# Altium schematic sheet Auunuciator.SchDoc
size A4
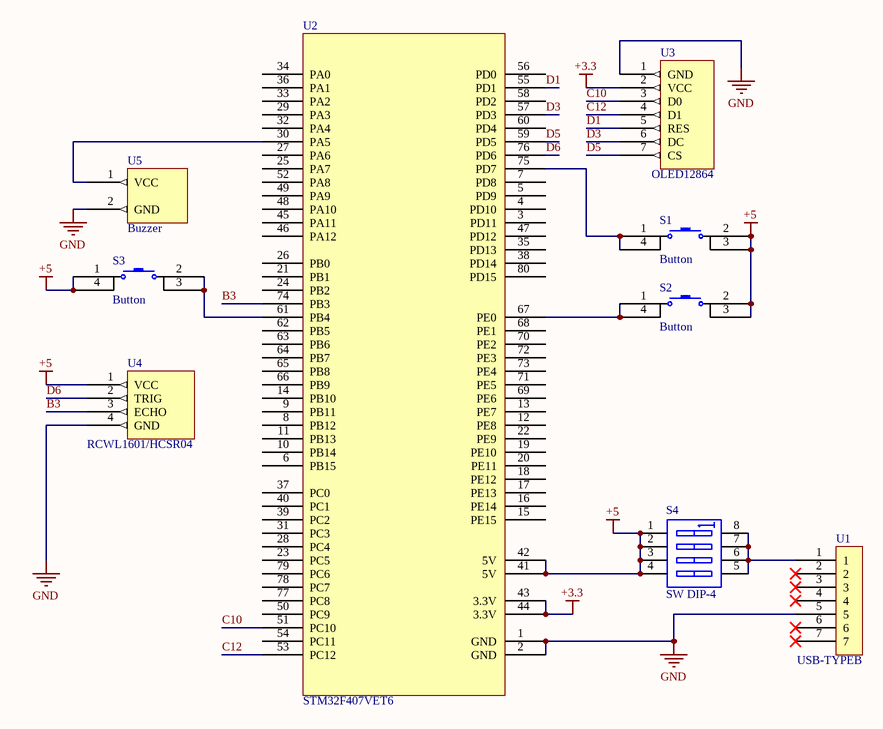
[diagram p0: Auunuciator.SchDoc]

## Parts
S1  Button
S2  Button
S3  Button
S4  SW DIP-4  [DIP-8]
U1  USB-TYPEB  [microB USB Breakout]
U2  STM32F407VET6  [FK407M1]
U3  OLED12864  [HDR1X7]
U4  RCWL1601/HCSR04  [HDR1X4]
U5  Buzzer  [THDZ]

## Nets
+3.3: U2.43(3.3V) U2.44(3.3V) U3.2(VCC)
+5: S1.2 S1.3 S2.2 S2.3 S3.1 S3.4 S4.1(A1) S4.2(A2) S4.3(A3) S4.4(A4) U2.41(5V) U2.42(5V) U4.1(VCC)
GND: U1.5 U2.1(GND) U2.2(GND) U3.1(GND) U4.4(GND) U5.2(GND)
B3: U2.74(PB3) U4.3(ECHO)
C10: U2.51(PC10) U3.3(D0)
C12: U2.53(PC12) U3.4(D1)
D1: U2.55(PD1) U3.5(RES)
D3: U2.57(PD3) U3.6(DC)
D5: U2.59(PD5) U3.7(CS)
D6: U2.76(PD6) U4.2(TRIG)
NetS1_1: S1.1 S1.4 U2.75(PD7)
NetS2_1: S2.1 S2.4 U2.67(PE0)
NetS3_2: S3.2 S3.3 U2.61(PB4)
NetS4_5: S4.5(B4) S4.6(B3) S4.7(B2) S4.8(B1) U1.1
NetU2_30: U2.30(PA5) U5.1(VCC)

Not connected (* = marked no-connect by the designer): U1 2* 3* 4* 6* 7*; U2 3(PD11) 4(PD10) 5(PD9) 6(PB15) 7(PD8) 8(PB12) 9(PB11) 10(PB14) 11(PB13) 12(PE8) 13(PE7) 14(PB10) 15(PE15) 16(PE14) 17(PE13) 18(PE12) 19(PE10) 20(PE11) 21(PB1) 22(PE9) 23(PC5) 24(PB2) 25(PA7) 26(PB0) 27(PA6) 28(PC4) 29(PA3) 31(PC3) 32(PA4) 33(PA2) 34(PA0) 35(PD13) 36(PA1) 37(PC0) 38(PD14) 39(PC2) 40(PC1) 45(PA11) 46(PA12) 47(PD12) 48(PA10) 49(PA9) 50(PC9) 52(PA8) 54(PC11) 56(PD0) 58(PD2) 60(PD4) 62(PB5) 63(PB6) 64(PB7) 65(PB8) 66(PB9) 68(PE1) 69(PE6) 70(PE2) 71(PE5) 72(PE3) 73(PE4) 77(PC8) 78(PC7) 79(PC6) 80(PD15)

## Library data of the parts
S1-S3 = 4PinButton
S4 = SW DIP-4: DIP Switch, 4 Position, SPST
U1 = HEAD7A
U2 = FK407M1
U3 = OLED12864: OLED
U4 = RCWL1601/HCSR04: Ranging Module
U5 = Buzzer: Active; pin to pad: 1>VCC 2>GND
